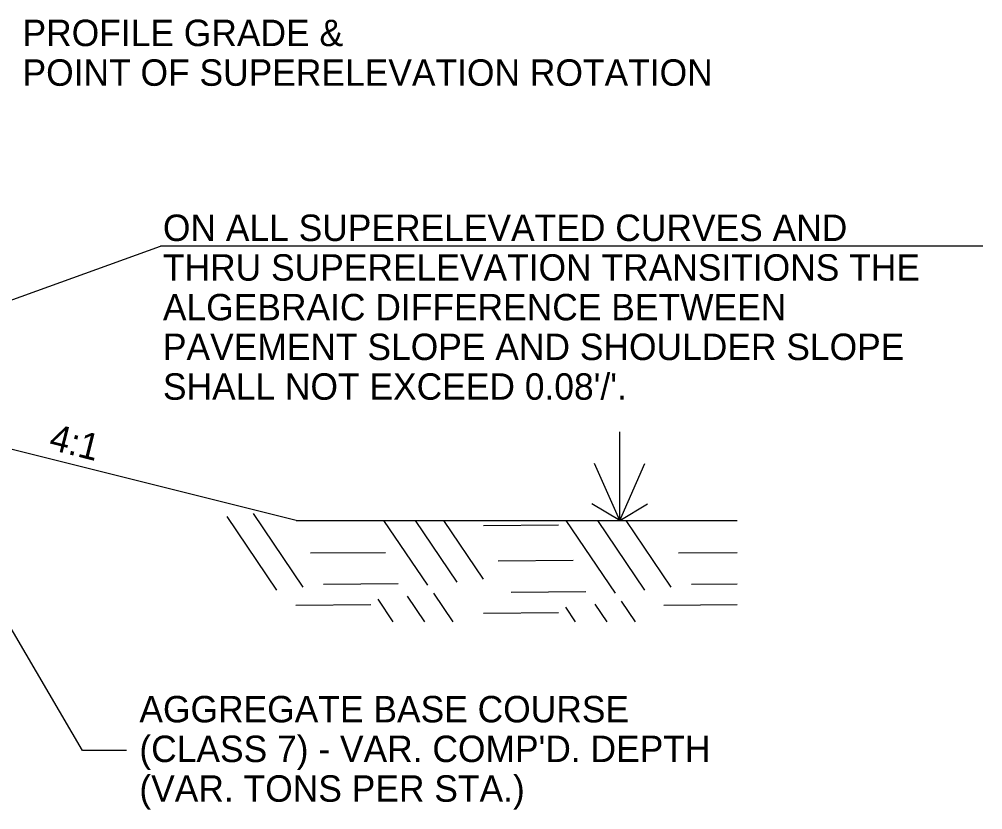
# Model space of a CAD drawing. Extents: x 1955768 to 1955917, y 566446 to 566546.
# Drawn here: x 1955858.54 to 1955880.38, y 566456.79 to 566474.72 of the extents above; entities that cross this region are included whole.
import ezdxf

# ---------------------------------------------------------------- set-up
doc = ezdxf.new("R2010")
doc.units = 0
for name, color, linetype in [('R_Border', 7, 'Continuous'), ('R_Grid', 7, 'Continuous'), ('R_Logo', 7, 'Continuous')]:
    doc.layers.add(name, color=color, linetype=linetype)

msp = doc.modelspace()

# ---------------------------------------------------------------- linework, layer by layer
at = {"layer": 'R_Border'}
for p, q in [((1955880.383, 566469.569), (1955861.743, 566469.569)), ((1955864.818, 566463.353), (1955851.173, 566466.764)), ((1955864.818, 566463.353), (1955874.818, 566463.353))]:
    msp.add_line(p, q, dxfattribs=at)
msp.add_lwpolyline([(1955853.512, 566466.604), (1955861.743, 566469.569)], dxfattribs=at)
at = {"layer": 'R_Grid'}
for p, q in [((1955864.38, 566461.773), (1955863.253, 566463.442)), ((1955864.978, 566461.842), (1955863.851, 566463.511)), ((1955867.8, 566461.884), (1955866.809, 566463.353)), ((1955868.468, 566461.953), (1955867.524, 566463.353)), ((1955869.066, 566462.023), (1955868.169, 566463.353)), ((1955872.055, 566461.703), (1955870.942, 566463.353)), ((1955872.723, 566461.773), (1955871.657, 566463.353)), ((1955873.321, 566461.842), (1955872.302, 566463.353)), ((1955870.762, 566463.247), (1955869.066, 566463.233)), ((1955866.841, 566462.621), (1955865.144, 566462.607)), ((1955871.096, 566462.44), (1955869.399, 566462.426)), ((1955874.818, 566462.618), (1955873.488, 566462.607)), ((1955867.133, 566461.912), (1955865.436, 566461.898)), ((1955874.818, 566461.906), (1955873.78, 566461.898)), ((1955867.018, 566461.054), (1955866.674, 566461.564)), ((1955867.732, 566461.054), (1955867.341, 566461.633)), ((1955868.377, 566461.054), (1955867.939, 566461.703)), ((1955871.388, 566461.731), (1955869.691, 566461.717)), ((1955866.507, 566461.439), (1955864.811, 566461.425)), ((1955871.151, 566461.054), (1955870.929, 566461.383)), ((1955871.865, 566461.054), (1955871.596, 566461.453)), ((1955872.51, 566461.054), (1955872.194, 566461.522)), ((1955874.818, 566461.438), (1955873.154, 566461.425)), ((1955870.762, 566461.258), (1955869.066, 566461.244))]:
    msp.add_line(p, q, dxfattribs=at)
msp.add_lwpolyline([(1955860.972, 566458.134), (1955859.972, 566458.134), (1955855.848, 566465.18)], dxfattribs=at)
at = {"layer": 'R_Logo'}
for q in [(1955872.154, 566465.361), (1955871.584, 566464.645), (1955872.723, 566464.645), (1955871.524, 566463.732), (1955872.783, 566463.732)]:
    msp.add_line((1955872.154, 566463.353), q, dxfattribs=at)

# ---------------------------------------------------------------- texts
at = {"layer": 'R_Border'}
for s, p in [('PROFILE GRADE & ', (1955858.614, 566474.109)), ('POINT OF SUPERELEVATION ROTATION', (1955858.614, 566473.209)), ('ON ALL SUPERELEVATED CURVES AND', (1955861.797, 566469.689)), ('THRU SUPERELEVATION TRANSITIONS THE', (1955861.797, 566468.789)), ('ALGEBRAIC DIFFERENCE BETWEEN', (1955861.797, 566467.889)), ('PAVEMENT SLOPE AND SHOULDER SLOPE', (1955861.797, 566466.989)), ("SHALL NOT EXCEED 0.08'/'.", (1955861.797, 566466.089)), ('AGGREGATE BASE COURSE', (1955861.263, 566458.772)), ("(CLASS 7) - VAR. COMP'D. DEPTH", (1955861.263, 566457.872)), ('(VAR. TONS PER STA.)', (1955861.263, 566456.972))]:
    msp.add_text(s, height=0.6, dxfattribs=at).set_placement(p)
msp.add_text('4:1', height=0.6, rotation=345.8549, dxfattribs=at).set_placement((1955859.187, 566464.97))

doc.saveas('drawing.dxf')
